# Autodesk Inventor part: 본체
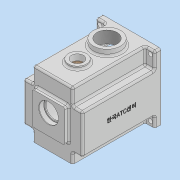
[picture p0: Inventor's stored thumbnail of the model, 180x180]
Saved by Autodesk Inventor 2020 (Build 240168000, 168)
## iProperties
Created: 2022-01
Part Number: 본체
Material: 일반
Document SubType Name: Modeling
Designer: user
Density: 1 g/cm^3
Appearance: 기본값
Mass: 555.176 g
Surface Area: 1187.47 cm^2
Volume: 555.176 cm^3
Author: user
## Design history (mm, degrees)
sketch "스케치1"
  geometry: L1 (-49, -50)-(49, -50); L2 (49, -50)-(49, 60); L3 (49, 60)-(-49, 60); L4 (-49, 60)-(-49, -50); 1 further point
  constraints: 8 end point, 2 parallel, 1 horizontal, 1 perpendicular
  dimensions: "d0" = 98 distance of L3.end L2.end; "d52" = 50 distance from line of L1 point (0, 0); "d53" = 110 distance between parallel lines of L1 L3
extrude "돌출1" new body sketch "스케치1" distance "d2" = 130; taper "d3" = 0 deg
sketch "스케치2"
  geometry: L1 (-49, 60)-(-49, -50) reference; L2 (-49, -50)-(49, -50) reference; L3 (49, -50)-(49, 60) reference; L4 (49, 60)-(-49, 60) reference; L5 (-49, 60)-(-33, 60); L6 (-33, 60)-(-33, 33); L7 (-33, 33)-(-49, 33); L8 (-49, 33)-(-49, 60); L9 (49, -50)-(49, 60) reference; L10 (49, 60)-(33, 60); L11 (33, 60)-(33, 33); L12 (33, 33)-(49, 33); L13 (49, 33)-(49, 60); L14 (-49, 60)-(-49, -50) reference; L15 (-49, -50)-(-33, -50); L16 (-33, -50)-(-33, -33); L17 (-33, -33)-(-49, -33); L18 (-49, -33)-(-49, -50); L19 (-49, -50)-(49, -50) reference; L20 (49, -50)-(33, -50); L21 (33, -50)-(33, -33); L22 (33, -33)-(49, -33); L23 (49, -33)-(49, -50); 9 further points
  constraints: 32 end point, 8 parallel, 4 horizontal, 4 perpendicular
  dimensions: "d6" = 16 distance of L6.end L7.end; "d7" = 27 distance of L5.end L6.end; "d8" = 16 distance of L12.end L11.end; "d9" = 27 distance of L11.end L10.end; "d10" = 16 distance of L17.end L16.end; "d11" = 17 distance of L16.end L15.end; "d12" = 16 distance of L21.end L22.end; "d13" = 17 distance of L20.end L21.end
extrude "돌출2" cut sketch "스케치2" distance "d14" = 120; taper "d15" = 0 deg
sketch "스케치3"
  geometry: L1 (-27, -22)-(27, -22); L2 (27, -22)-(27, 32); L3 (27, 32)-(-27, 32); L4 (-27, 32)-(-27, -22); L5 (33, 60)-(-33, 60) reference; L6 (-27, 32)-(27, -22); L7 (27, 32)-(-27, -22)
  constraints: 12 end point, 2 parallel, 1 horizontal, 1 perpendicular
  dimensions: "d16" = 54 distance of L3.end L2.end; "d17" = 54 distance of L2.end L1.end; "d78" = 28 distance between parallel lines of L3 L5
extrude "돌출3" join sketch "스케치3" distance "d18" = 7; taper "d19" = 0 deg
sketch "스케치6"
  geometry: L1 (-23, 50)-(23, 50); L2 (23, 50)-(23, 25.666); L3 (23, 25.666)-(-23, 25.666); L4 (-23, 25.666)-(-23, 50); L5 (-23, 50)-(23, 25.666); L6 (23, 50)-(-23, 25.666); C1 r 42 at (0, 0); 5 further points
  constraints: 12 end point, 3 midpoint, 2 parallel, 1 centre point, 1 coincident, 1 horizontal, 1 perpendicular, 1 vertical alignment
  dimensions: "d24" = 84 diameter of C1; "d25" = 46 distance of L2.end L3.end; "d26" = 50 distance from line of L1 point (0, 0)
extrude "돌출5" cut sketch "스케치6" distance "d27" = 114; taper "d28" = 0 deg
sketch "스케치14"
  geometry: L1 (-23, 35.143)-(-23, 50) reference; L2 (23, 50)-(23, 35.143) reference; L3 (-23, 50)-(23, 50) reference; L4 (-26, 36.729)-(-26, 53); L5 (-26, 53)-(26, 53); L6 (26, 53)-(26, 36.729); A1 r 42 centre (0, 0) between (-23, 35.143) and (23, 35.143) reference; A2 r 45 centre (0, 0) between (-26, 36.729) and (26, 36.729); 1 further point
  constraints: 6 end point, 2 point on circle, 1 centre point, 3 other
  dimensions: "d51" = 3 radial gap between concentric circles of A1 A2
  node "투영된 루프3"
sketch "스케치15"
  geometry: 1 further point
extrude "돌출13" cut sketch "스케치14" distance "d54" = 9; taper "d55" = 0 deg
sketch "스케치17"
  geometry: C1 r 21 at (0, 11); C2 r 15 at (0, -20); 3 further points
  constraints: 2 centre point
  dimensions: "d60" = 42 diameter of C1; "d61" = 30 diameter of C2; "d62" = 20 distance of C2.centre point (0, 0); "d63" = 11 distance of point (0, 0) C1.centre
extrude "돌출14" join sketch "스케치17" distance "d64" = 7; taper "d65" = 0 deg
node "작업 평면1"
sketch "스케치19"
  geometry: L1 (98, 0)-(0, 0) reference; C1 r 22.5 at (49, -40); 1 further point
  constraints: 1 centre point
  dimensions: "d70" = 45 diameter of C1; "d71" = 40 distance of C1.centre point (49, 0)
extrude "돌출16" join sketch "스케치19" stored distance "d72" = 10; taper "d73" = 0 deg
sketch "스케치22"
  geometry: C1 r 11 at (0, -20); A1 r 15 centre (0, -20) between (-8.978, -7.984) and (8.978, -7.984) reference; A2 r 21 centre (0, 11) between (8.978, -7.984) and (-8.978, -7.984) reference; 1 further point
  constraints: 1 centre point, 1 coincident
  dimensions: "d84" = 22 diameter of C1
  node "투영된 루프6"
node "작업 평면2"
sketch "스케치23"
  geometry: C1 r 22.5 at (49, -40) reference; C2 r 15 at (49, -89); 1 further point
  constraints: 1 centre point
  dimensions: "d80" = 30 diameter of C2; "d81" = 49 distance of C1.centre C2.centre
extrude "돌출18" join sketch "스케치23" stored distance "d82" = 7; taper "d83" = 0 deg
sketch "스케치24"
  geometry: L1 (-26, 36.729)-(-26, 53) reference; L2 (-26, 53)-(26, 53) reference; L3 (26, 53)-(26, 36.729) reference; L4 (49, 60)-(49, -50) reference; L5 (-49, 60)-(49, 60) reference; L6 (-49, -50)-(-49, 60) reference; L7 (49, -50)-(-49, -50) reference; L8 (42, -43)-(-42, -43); L9 (-42, -43)-(-42, 53); L10 (-42, 53)-(42, 53); L11 (42, 53)-(42, -43); C1 r 3.5 at (-42, 53); C2 r 3.5 at (42, 53); C3 r 3.5 at (42, -43); C4 r 3.5 at (-42, -43); A1 r 45 centre (0, 0) between (-26, 36.729) and (26, 36.729) reference; 1 further point
  constraints: 8 end point, 4 centre point, 4 coincident, 2 parallel, 1 horizontal, 1 perpendicular
  dimensions: "d85" = 84 distance of L9.end L10.end; "d86" = 96 distance of L8.end L9.end; "d87" = 7 distance between parallel lines of L5 L10; "d88" = 7 distance between parallel lines of L9 L6; "d89" = 7 diameter of C1; "d90" = 7 diameter of C2; "d91" = 7 diameter of C3; "d92" = 7 diameter of C4
extrude "돌출19" cut sketch "스케치24" extent not by distance; stored distance "d93" = 0; taper "d94" = 0 deg
sketch "스케치25"
  geometry: C1 r 22.5 at (0, 0) reference; 2 further points
  constraints: 1 coincident
hole "구멍1" sketch "스케치25" at (0, 0) diameter "d95" = 33.376; stored, may be unused: countersink angle "d99" = 90 deg, drill point angle "d101" = 118 deg; dims "d96" = 70, "d97" = 4, "d98" = 2, "d100" = 77.3
sketch "스케치26"
  geometry: C1 r 15 at (0, 0) reference; C2 r 10 at (0, 0); 1 further point
  constraints: 1 centre point, 1 coincident
  dimensions: "d102" = 20 diameter of C2
extrude "돌출20" cut sketch "스케치26" distance "d103" = 53; taper "d104" = 0 deg
extrude "돌출21" cut sketch "스케치22" distance "d105" = 7; taper "d106" = 0 deg
sketch "스케치27"
  geometry: C1 r 11 at (0, 0) reference; C2 r 9.5 at (0, 0); 1 further point
  constraints: 1 centre point, 1 coincident
  dimensions: "d107" = 19 diameter of C2
extrude "돌출22" cut sketch "스케치27" distance "d108" = 3; taper "d109" = 0 deg
sketch "스케치28"
  geometry: C1 r 11 at (0, -20) reference; C2 r 17.5 at (0, 11); A1 r 15 centre (0, -20) between (-8.978, -7.984) and (8.978, -7.984) reference; A2 r 21 centre (0, 11) between (8.978, -7.984) and (-8.978, -7.984) reference; 1 further point
  constraints: 1 centre point, 1 coincident
  dimensions: "d110" = 35 diameter of C2
extrude "돌출23" cut sketch "스케치28" distance "d111" = 10; taper "d112" = 0 deg
sketch "스케치33"
  geometry: C1 r 17.5 at (0, 0) reference; C2 r 17.5 at (0, 0) reference; C3 r 17.5 at (0, 0); 1 further point
  constraints: 1 centre point, 1 coincident
  dimensions: "d122" = 35 diameter of C3
extrude "돌출27" cut sketch "스케치33" distance "d123" = 10; taper "d124" = 0 deg
sketch "스케치34"
  geometry: C1 r 17.5 at (0, 0) reference; C2 r 14 at (0, 0); 1 further point
  constraints: 1 centre point, 1 coincident
  dimensions: "d125" = 28 diameter of C2
extrude "돌출28" cut sketch "스케치34" extent not by distance; stored distance "d126" = 20; taper "d127" = 0 deg
sketch "스케치35"
  geometry: C1 r 14 at (0, 11) reference; C2 r 16 at (0, 11); 1 further point
  constraints: 1 centre point, 1 coincident
  dimensions: "d128" = 32 diameter of C2
extrude "돌출29" cut sketch "스케치35" distance "d129" = 0.8; taper "d130" = 0 deg
node "작업 평면3"
sketch "스케치36"
  geometry: C1 r 16 at (0, 11) reference; C2 r 16 at (0, 11); 1 further point
  constraints: 1 centre point, 1 coincident
  dimensions: "d132" = 32 diameter of C2
extrude "돌출30" cut sketch "스케치36" distance "d133" = 7.5; taper "d134" = 0 deg
sketch "스케치37" dims "d135" = 72
  geometry: L1 (-36, 4)-(-41.809, 4); L2 (-36, -4)-(-41.809, -4); A1 r 4 centre (-36, 0) between (-36, 4) and (-36, -4); A2 r 42 centre (0, 0) between (-23, 35.143) and (23, 35.143) reference; 2 further points
  constraints: 4 end point, 4 point on circle, 2 horizontal alignment, 2 tangent, 1 centre point, 1 coincident, 1 horizontal, 1 parallel, 2 other
  dimensions: "d137" = 8 diameter of A1
fillet "모깎기1" dims "d138" = 3
fillet "모깎기2" dims "d139" = 3
fillet "모깎기3" dims "d140" = 3
fillet "모깎기4" dims "d141" = 0.3
chamfer "모따기1" distance "d142" = 1; stored, may be unused: second distance "d143" = 2, angle "d144" = 30 deg
chamfer "모따기2" distance "d145" = 0.8; stored, may be unused: second distance "d146" = 2, angle "d147" = 30 deg
fillet "모깎기5" dims "d148" = 3
fillet "모깎기6" dims "d149" = 3
fillet "모깎기7" dims "d150" = 3
fillet "모깎기8" dims "d151" = 3
fillet "모깎기9" dims "d152" = 3
sketch "스케치38"
  geometry: L1 (-130, 107)-(-130, 86) reference; L2 (-13, 83)-(-127, 83) reference; 2 further points
  constraints: 1 other
  dimensions: "d153" = 65 distance from line of L1 point (-65, 50); "d154" = 33 distance from line of L2 point (-65, 50)
feature "엠보싱1" sketch "스케치38" dims "d155" = 0.5, "d156" = 0
extrude "돌출31" join sketch "스케치37" stored distance "d157" = 0.8; taper "d158" = 0 deg
sketch "스케치39"
  geometry: L1 (-36, 4)-(-41.809, 4) reference; L2 (-41.809, -4)-(-36, -4) reference; L3 (36, 4)-(41.809, 4) reference; L4 (41.809, -4)-(36, -4) reference; A1 r 42 centre (0, 0) between (-41.809, 4) and (-41.809, -4) reference; A2 r 4 centre (-36, 0) between (-36, -4) and (-36, 4) reference; A3 r 4 centre (36, 0) between (36, 4) and (36, -4) reference; A4 r 42 centre (0, 0) between (41.809, -4) and (41.809, 4) reference; 1 further point
hole "구멍2" sketch "스케치39" at (-36, 0), (36, 0) diameter "d159" = 3.242; stored, may be unused: countersink angle "d163" = 90 deg, drill point angle "d165" = 118 deg; dims "d160" = 7, "d161" = 4, "d162" = 2, "d164" = 9
fillet "모깎기10" dims "d166" = 6
fillet "모깎기11" dims "d167" = 3
fillet "모깎기12" dims "d168" = 6
fillet "모깎기13" dims "d169" = 3
fillet "모깎기14" dims "d170" = 3
fillet "모깎기15" dims "d171" = 3
node "작업 평면4"
sketch "스케치40"
  geometry: C1 r 10 at (0, 0) reference; C2 r 15 at (0, 0) reference; C3 r 15 at (0, 0); 1 further point
  constraints: 1 centre point, 1 coincident
  dimensions: "d173" = 30 diameter of C3
extrude "돌출32" cut sketch "스케치40" distance "d174" = 5; taper "d175" = 0 deg
chamfer "모따기3" distance "d176" = 1; stored, may be unused: second distance "d177" = 2, angle "d178" = 30 deg
sketch "스케치41"
  geometry: C1 r 42 at (0, 0); 1 further point
  constraints: 1 centre point, 1 coincident
extrude "돌출33" cut sketch "스케치41" distance "d179" = 42.5; taper "d180" = 0 deg
fillet "모깎기16" dims "d181" = 3
node "솔리드1"
mirror "미러1"
node "투영된 루프1"
node "투영된 루프7"
node "투영된 루프8"
node "투영된 루프9"
node "투영된 루프14"
node "투영된 루프15"
node "투영된 루프16"
node "투영된 루프17"
node "투영된 루프18"
feature "A9D066F2-1C7D-4E18-AEED-F7BC21143FA4" dims "d95" = 33.376, "d96" = 70, "d97" = 4, "d98" = 2, "d99" = 90 deg, "d100" = 77.3, "d101" = 118 deg
other parameters: "d79" = 5, "d131" = -0.8
